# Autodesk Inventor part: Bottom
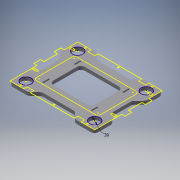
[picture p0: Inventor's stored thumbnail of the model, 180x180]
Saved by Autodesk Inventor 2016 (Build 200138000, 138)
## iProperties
Created: 2015-11
Part Number: Bottom
Material: Generic
Document SubType Name: Modeling
Designer: John
Density: 1 g/cm^3
Appearance: Default
Author: John
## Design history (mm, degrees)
sketch "Sketch1"
  geometry: L1 (317.1, -50.8)-(317.1, -35.8) reference; L2 (317.1, -35.8)-(309.3, -35.8) reference; L3 (309.3, -35.8)-(309.3, -37.325) reference; L4 (309.3, -37.325)-(302.3, -37.325) reference; L5 (302.3, -37.325)-(302.3, -35.8) reference; L6 (302.3, -35.8)-(296.3, -35.8) reference; L7 (296.3, -35.8)-(296.3, -30.6) reference; L8 (296.3, -30.6)-(302.3, -30.6) reference; L9 (302.3, -30.6)-(302.3, -29.075) reference; L10 (302.3, -29.075)-(309.3, -29.075) reference; L11 (309.3, -29.075)-(309.3, -30.6) reference; L12 (309.3, -30.6)-(317.1, -30.6) reference; L13 (317.1, -30.6)-(317.1, 0) reference; L14 (317.1, 0)-(266.7, 0) reference; L15 (266.7, 0)-(266.7, -12.9) reference; L16 (266.7, -12.9)-(240.9, -12.9) reference; L17 (240.9, -12.9)-(240.9, 0) reference; L18 (240.9, 0)-(76.2, 0) reference; L19 (76.2, 0)-(76.2, -12.9) reference; L20 (76.2, -12.9)-(50.4, -12.9) reference; L21 (50.4, 0)-(50.4, -12.9) reference; L22 (0, 0)-(50.4, 0) reference; L23 (0, 0)-(0, -30.6) reference; L24 (0, -30.6)-(7.8, -30.6) reference; L25 (7.8, -30.6)-(7.8, -29.075) reference; L26 (7.8, -29.075)-(14.8, -29.075) reference; L27 (14.8, -29.075)-(14.8, -30.6) reference; L28 (14.8, -30.6)-(20.8, -30.6) reference; L29 (20.8, -30.6)-(20.8, -35.8) reference; L30 (20.8, -35.8)-(14.8, -35.8) reference; L31 (14.8, -35.8)-(14.8, -37.325) reference; L32 (14.8, -37.325)-(7.8, -37.325) reference; L33 (7.8, -37.325)-(7.8, -35.8) reference; L34 (7.8, -35.8)-(0, -35.8) reference; L35 (0, -35.8)-(0, -50.8) reference; L36 (0, -50.8)-(-12.9, -50.8) reference; L37 (-12.9, -50.8)-(-12.9, -76.2) reference; L38 (-12.9, -76.2)-(0, -76.2) reference; L39 (0, -76.2)-(0, -127) reference; L40 (0, -127)-(-12.9, -127) reference; L41 (-12.9, -127)-(-12.9, -152.4) reference; L42 (-12.9, -152.4)-(-0.4, -152.4) reference; L43 (-0.4, -152.4)-(-0.4, -254) reference; L44 (-0.4, -254)-(50.8, -254) reference; L45 (50.8, -254)-(50.8, -241.1) reference; L46 (50.8, -241.1)-(75.8, -241.1) reference; L47 (75.8, -254)-(75.8, -241.1) reference; L48 (241.3, -254)-(75.8, -254) reference; L49 (241.3, -241.1)-(241.3, -254) reference; L50 (241.3, -241.1)-(266.3, -241.1) reference; L51 (266.3, -254)-(266.3, -241.1) reference; L52 (317.5, -254)-(266.3, -254) reference; L53 (317.5, -254)-(317.5, -152.4) reference; L54 (330, -152.4)-(317.5, -152.4) reference; L55 (330, -127)-(330, -152.4) reference; L56 (317.1, -127)-(330, -127) reference; L57 (317.1, -127)-(317.1, -76.2) reference; L58 (317.1, -76.2)-(330, -76.2) reference; L59 (330, -76.2)-(330, -50.8) reference; L60 (330, -50.8)-(317.1, -50.8) reference; L61 (-0.2, -172.6)-(7.8, -172.6) reference; L62 (-0.2, -167.4)-(-0.2, -172.6) reference; L63 (7.8, -167.4)-(-0.2, -167.4) reference; L64 (7.8, -165.875)-(7.8, -167.4) reference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; C1 r 2.5 at (29.6, -224) reference; C2 r 2.5 at (29.6, -30) reference; C3 r 2.5 at (287.5, -30) reference; C4 r 2.5 at (287.5, -224) reference; C5 r 2.6 at (33, -247.35) reference; C6 r 2.6 at (158.55, -247.35) reference; C7 r 2.6 at (284.1, -247.35) reference; C8 r 2.6 at (284.1, -6.35) reference; C9 r 2.6 at (158.55, -6.35) reference; C10 r 2.6 at (33, -6.35) reference; C11 r 19.5 at (29.6, -30); C12 r 19.5 at (29.6, -224); C13 r 19.5 at (287.5, -224); C14 r 19.5 at (287.5, -30); A1 r 10 centre (269.2, -60.8) between (279.2, -60.8) and (269.2, -50.8) reference; A2 r 10 centre (269.2, -193.2) between (269.2, -203.2) and (279.2, -193.2) reference; A3 r 10 centre (47.9, -193.2) between (37.9, -193.2) and (47.9, -203.2) reference; A4 r 10 centre (47.9, -60.8) between (47.9, -50.8) and (37.9, -60.8) reference
  constraints: 4 centre point, 4 coincident, 3 equal radius
  dimensions: "d0" = 39 diameter of C13
  node "Reference1"
sketch "Sketch2"
  geometry: L1 (-2.6, 2.2)-(319.7, 2.2); L2 (319.7, 2.2)-(319.7, -256.2); L3 (319.7, -256.2)-(-2.6, -256.2); L4 (-2.6, -256.2)-(-2.6, 2.2); C1 r 19.5 at (29.6, -224) reference; C2 r 19.5 at (29.6, -30) reference; C3 r 19.5 at (287.5, -30) reference; C4 r 19.5 at (287.5, -224) reference; 1 further point
  constraints: 8 end point, 2 parallel, 1 horizontal, 1 perpendicular
  dimensions: "d2" = 32.2 distance from line of L4 C2.centre (computed from d3); "d3" = 39 diameter of C2 (derived); "d4" = 32.2 distance from line of C3.centre L2 (= d2); "d5" = 32.2 distance from line of C1.centre L3 (= d2); "d6" = 32.2 distance from line of C2.centre L1 (= d5)
extrude "Extrusion1" new body sketch "Sketch2" distance "d7" = 12.7; taper "d8" = 0 deg
fillet "Fillet1" dims "d9" = 15
sketch "Sketch3"
  geometry: L1 (12.4, 2.2)-(304.7, 2.2) reference; L2 (-2.6, -241.2)-(-2.6, -12.8) reference; L3 (304.7, -256.2)-(12.4, -256.2) reference; L4 (319.7, -12.8)-(319.7, -241.2) reference; L5 (67.4, -57.8)-(67.4, -77.8); L6 (64.775, -57.8)-(64.775, -77.8); L7 (70.025, -77.8)-(70.025, -57.8); L8 (67.4, -176.2)-(67.4, -196.2); L9 (64.775, -176.2)-(64.775, -196.2); L10 (70.025, -196.2)-(70.025, -176.2); L11 (249.7, -176.2)-(249.7, -196.2); L12 (247.075, -176.2)-(247.075, -196.2); L13 (252.325, -196.2)-(252.325, -176.2); L14 (249.7, -57.8)-(249.7, -77.8); L15 (247.075, -57.8)-(247.075, -77.8); L16 (252.325, -77.8)-(252.325, -57.8); L17 (67.4, -67.8)-(249.7, -67.8); L18 (249.7, -67.8)-(249.7, -186.2); L19 (249.7, -186.2)-(67.4, -186.2); L20 (67.4, -186.2)-(67.4, -67.8); C1 r 19.5 at (287.5, -224) reference; C2 r 19.5 at (287.5, -30) reference; C3 r 19.5 at (29.6, -30) reference; C4 r 19.5 at (29.6, -224) reference; A1 r 15 centre (304.7, -12.8) between (319.7, -12.8) and (304.7, 2.2) reference; A2 r 15 centre (12.4, -12.8) between (12.4, 2.2) and (-2.6, -12.8) reference; A3 r 15 centre (12.4, -241.2) between (-2.6, -241.2) and (12.4, -256.2) reference; A4 r 15 centre (304.7, -241.2) between (304.7, -256.2) and (319.7, -241.2) reference; A5 r 2.625 centre (67.4, -57.8) between (70.025, -57.8) and (64.775, -57.8); A6 r 2.625 centre (67.4, -77.8) between (64.775, -77.8) and (70.025, -77.8); A7 r 2.625 centre (67.4, -176.2) between (70.025, -176.2) and (64.775, -176.2); A8 r 2.625 centre (67.4, -196.2) between (64.775, -196.2) and (70.025, -196.2); A9 r 2.625 centre (249.7, -176.2) between (252.325, -176.2) and (247.075, -176.2); A10 r 2.625 centre (249.7, -196.2) between (247.075, -196.2) and (252.325, -196.2); A11 r 2.625 centre (249.7, -57.8) between (252.325, -57.8) and (247.075, -57.8); A12 r 2.625 centre (249.7, -77.8) between (247.075, -77.8) and (252.325, -77.8); 3 further points
  constraints: 40 end point, 16 point on circle, 16 tangent, 8 centre point, 8 parallel, 4 midpoint, 3 equal length, 3 equal radius, 2 coincident, 2 point on line, 1 horizontal, 1 perpendicular, 1 vertical
  dimensions: "d10" = 2.625 radius of A5; "d11" = 70 distance between parallel lines of L2 L20; "d12" = 70 distance between parallel lines of L4 L18 (= d11); "d13" = 70 distance between parallel lines of L3 L19; "d14" = 70 distance between parallel lines of L1 L17 (= d13); "d15" = 20 distance of L8.start L8.end
extrude "Extrusion2" cut sketch "Sketch3" distance "d16" = 12.7; taper "d17" = 0 deg
sketch "Sketch4"
  geometry: L1 (247.075, -77.8)-(247.075, -57.8) reference; L2 (252.325, -57.8)-(252.325, -77.8) reference; L3 (64.775, -196.2)-(64.775, -176.2) reference; L4 (70.025, -176.2)-(70.025, -196.2) reference; L5 (64.775, -77.8)-(64.775, -57.8) reference; L6 (70.025, -57.8)-(70.025, -77.8) reference; L7 (247.075, -196.2)-(247.075, -176.2) reference; L8 (252.325, -176.2)-(252.325, -196.2) reference; L9 (12.4, 2.2)-(304.7, 2.2) reference; L10 (-2.6, -241.2)-(-2.6, -12.8) reference; L11 (304.7, -256.2)-(12.4, -256.2) reference; L12 (319.7, -12.8)-(319.7, -241.2) reference; L13 (-2.6, -64.1)-(22.8, -89.5); L14 (22.8, -89.5)-(22.8, -164.5); L15 (22.8, -164.5)-(-2.6, -189.9); L16 (319.7, -189.9)-(294.3, -164.5); L17 (294.3, -164.5)-(294.3, -89.5); L18 (294.3, -89.5)-(319.7, -64.1); L19 (70.65, 2.2)-(96.05, -23.2); L20 (96.05, -23.2)-(221.05, -23.2); L21 (221.05, -23.2)-(246.45, 2.2); L22 (319.7, -12.8)-(319.7, -241.2) reference; L23 (70.65, -256.2)-(96.05, -230.8); L24 (96.05, -230.8)-(221.05, -230.8); L25 (221.05, -230.8)-(246.45, -256.2); L26 (12.4, 2.2)-(304.7, 2.2) reference; L27 (70.65, 2.2)-(246.45, 2.2); C1 r 19.5 at (287.5, -224) reference; C2 r 19.5 at (287.5, -30) reference; C3 r 19.5 at (29.6, -30) reference; C4 r 19.5 at (29.6, -224) reference; A1 r 2.625 centre (249.7, -77.8) between (247.075, -77.8) and (252.325, -77.8) reference; A2 r 2.625 centre (249.7, -57.8) between (252.325, -57.8) and (247.075, -57.8) reference; A3 r 2.625 centre (67.4, -196.2) between (64.775, -196.2) and (70.025, -196.2) reference; A4 r 2.625 centre (67.4, -176.2) between (70.025, -176.2) and (64.775, -176.2) reference; A5 r 2.625 centre (67.4, -77.8) between (64.775, -77.8) and (70.025, -77.8) reference; A6 r 2.625 centre (67.4, -57.8) between (70.025, -57.8) and (64.775, -57.8) reference; A7 r 2.625 centre (249.7, -196.2) between (247.075, -196.2) and (252.325, -196.2) reference; A8 r 2.625 centre (249.7, -176.2) between (252.325, -176.2) and (247.075, -176.2) reference; A9 r 15 centre (304.7, -12.8) between (319.7, -12.8) and (304.7, 2.2) reference; A10 r 15 centre (12.4, -12.8) between (12.4, 2.2) and (-2.6, -12.8) reference; A11 r 15 centre (12.4, -241.2) between (-2.6, -241.2) and (12.4, -256.2) reference; A12 r 15 centre (304.7, -241.2) between (304.7, -256.2) and (319.7, -241.2) reference; 7 further points
  constraints: 26 end point, 8 point on line, 6 midpoint, 5 equal length, 2 horizontal alignment, 2 vertical alignment, 1 collinear, 1 horizontal, 1 parallel, 1 perpendicular, 1 vertical
  dimensions: "d18" = 25.4 distance between parallel lines of L10 L14; "d19" = 75 distance of L13.end L14.end; "d20" = 45 deg angle of L10 L15; "d21" = 45 deg angle of L12 L16 (= d20); "d22" = 45 deg angle of L11 L25 (= d20); "d23" = 45 deg angle of L11 L23 (= d20); "d24" = 45 deg angle of L9 L19 (= d20); "d25" = 45 deg angle of L9 L21 (= d24); "d26" = 25.4 distance between parallel lines of L26 L20 (= d18); "d27" = 25.4 distance between parallel lines of L11 L24 (= d18); "d28" = 125 distance of L19.end L20.end
  node "Projected Loop2"
extrude "Extrusion3" cut sketch "Sketch4" distance "d29" = 12.7; taper "d30" = 0 deg
extrude "Extrusion4" cut sketch "Sketch4" distance "d31" = 12.7; taper "d32" = 0 deg
fillet "Fillet2" dims "d33" = 15
sketch "Sketch5"
  geometry: L1 (247.075, -77.8)-(247.075, -57.8) reference; L2 (252.325, -57.8)-(252.325, -77.8) reference; L3 (64.775, -196.2)-(64.775, -176.2) reference; L4 (70.025, -176.2)-(70.025, -196.2) reference; L5 (64.775, -77.8)-(64.775, -57.8) reference; L6 (70.025, -57.8)-(70.025, -77.8) reference; L7 (247.075, -196.2)-(247.075, -176.2) reference; L8 (252.325, -176.2)-(252.325, -196.2) reference; L9 (315.307, -185.507)-(298.693, -168.893) reference; L10 (294.3, -158.287)-(294.3, -95.713) reference; L11 (298.693, -85.107)-(315.307, -68.493) reference; L12 (319.7, -12.8)-(319.7, -57.887) reference; L13 (252.663, 2.2)-(304.7, 2.2) reference; L14 (242.057, -2.193)-(225.443, -18.807) reference; L15 (214.837, -23.2)-(102.263, -23.2) reference; L16 (91.657, -18.807)-(75.043, -2.193) reference; L17 (12.4, 2.2)-(64.437, 2.2) reference; L18 (-2.6, -57.887)-(-2.6, -12.8) reference; L19 (1.793, -68.493)-(18.407, -85.107) reference; L20 (22.8, -95.713)-(22.8, -158.287) reference; L21 (18.407, -168.893)-(1.793, -185.507) reference; L22 (-2.6, -241.2)-(-2.6, -196.113) reference; L23 (64.437, -256.2)-(12.4, -256.2) reference; L24 (75.043, -251.807)-(91.657, -235.193) reference; L25 (102.263, -230.8)-(214.837, -230.8) reference; L26 (225.443, -235.193)-(242.057, -251.807) reference; L27 (304.7, -256.2)-(252.663, -256.2) reference; L28 (319.7, -196.113)-(319.7, -241.2) reference; L29 (80.1, -67.8)-(237, -67.8); L30 (237, -67.8)-(237, -186.2); L31 (237, -186.2)-(80.1, -186.2); L32 (80.1, -186.2)-(80.1, -67.8); C1 r 19.5 at (287.5, -224) reference; C2 r 19.5 at (287.5, -30) reference; C3 r 19.5 at (29.6, -30) reference; C4 r 19.5 at (29.6, -224) reference; A1 r 2.625 centre (249.7, -77.8) between (247.075, -77.8) and (252.325, -77.8) reference; A2 r 2.625 centre (249.7, -57.8) between (252.325, -57.8) and (247.075, -57.8) reference; A3 r 2.625 centre (67.4, -196.2) between (64.775, -196.2) and (70.025, -196.2) reference; A4 r 2.625 centre (67.4, -176.2) between (70.025, -176.2) and (64.775, -176.2) reference; A5 r 2.625 centre (67.4, -77.8) between (64.775, -77.8) and (70.025, -77.8) reference; A6 r 2.625 centre (67.4, -57.8) between (70.025, -57.8) and (64.775, -57.8) reference; A7 r 2.625 centre (249.7, -196.2) between (247.075, -196.2) and (252.325, -196.2) reference; A8 r 2.625 centre (249.7, -176.2) between (252.325, -176.2) and (247.075, -176.2) reference; A9 r 15 centre (304.7, -196.113) between (319.7, -196.113) and (315.307, -185.507) reference; A10 r 15 centre (309.3, -158.287) between (294.3, -158.287) and (298.693, -168.893) reference; A11 r 15 centre (309.3, -95.713) between (298.693, -85.107) and (294.3, -95.713) reference; A12 r 15 centre (304.7, -57.887) between (315.307, -68.493) and (319.7, -57.887) reference; A13 r 15 centre (304.7, -12.8) between (319.7, -12.8) and (304.7, 2.2) reference; A14 r 15 centre (252.663, -12.8) between (252.663, 2.2) and (242.057, -2.193) reference; A15 r 15 centre (214.837, -8.2) between (214.837, -23.2) and (225.443, -18.807) reference; A16 r 15 centre (102.263, -8.2) between (91.657, -18.807) and (102.263, -23.2) reference; A17 r 15 centre (64.437, -12.8) between (75.043, -2.193) and (64.437, 2.2) reference; A18 r 15 centre (12.4, -12.8) between (12.4, 2.2) and (-2.6, -12.8) reference; A19 r 15 centre (12.4, -57.887) between (-2.6, -57.887) and (1.793, -68.493) reference; A20 r 15 centre (7.8, -95.713) between (22.8, -95.713) and (18.407, -85.107) reference; A21 r 15 centre (7.8, -158.287) between (18.407, -168.893) and (22.8, -158.287) reference; A22 r 15 centre (12.4, -196.113) between (1.793, -185.507) and (-2.6, -196.113) reference; A23 r 15 centre (12.4, -241.2) between (-2.6, -241.2) and (12.4, -256.2) reference; A24 r 15 centre (64.437, -241.2) between (64.437, -256.2) and (75.043, -251.807) reference; A25 r 15 centre (102.263, -245.8) between (102.263, -230.8) and (91.657, -235.193) reference; A26 r 15 centre (214.837, -245.8) between (225.443, -235.193) and (214.837, -230.8) reference; A27 r 15 centre (252.663, -241.2) between (242.057, -251.807) and (252.663, -256.2) reference; A28 r 15 centre (304.7, -241.2) between (304.7, -256.2) and (319.7, -241.2) reference; 1 further point
  constraints: 8 end point, 2 parallel, 1 horizontal, 1 perpendicular
  dimensions: "d34" = 12.7 distance from line of A4.centre L32; "d35" = 12.7 distance from line of A8.centre L30 (= d34); "d36" = 10 distance from line of A3.centre L31; "d37" = 10 distance from line of A6.centre L29 (= d36)
extrude "Extrusion5" cut sketch "Sketch5" distance "d38" = 12.7; taper "d39" = 0 deg
fillet "Fillet3" dims "d40" = 15
body "Solid1"
node "Projected Loop1"
node "Projected Loop3"
